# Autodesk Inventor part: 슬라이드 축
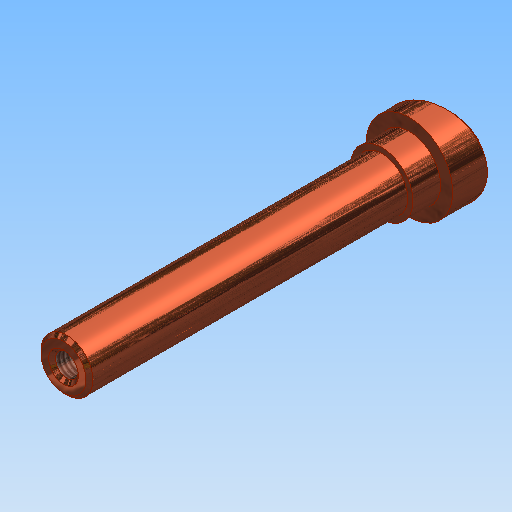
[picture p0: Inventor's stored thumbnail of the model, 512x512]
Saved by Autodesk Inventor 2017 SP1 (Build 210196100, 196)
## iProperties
Created: 2021-07
Part Number: 슬라이드 축
Document SubType Name: 모델링
Designer: mdu
Mass: 21.572 g
Surface Area: 67.5858 cm^2
Volume: 21.572 cm^3
Density: 1 g/cm^3
Material: 일반
Appearance: 금속 1400F 열
변환 표준: STEP AP214IS
파일 이름: C:\Users\SeoGD\Desktop\?쒗뿕\異?stp
전처리기: Build: 253, Release: 2010 SP1 - Date: Wed 07/29/2009
전송 단위: 밀리미터
불확실성: 0.01
Author: mdu
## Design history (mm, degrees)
sketch "스케치1"
  geometry: L1 (0, 100)-(7.5, 100); L2 (7.5, 100)-(7.5, 0); L3 (7.5, 0)-(12.5, 0); L4 (12.5, 0)-(12.5, -17); L5 (12.5, -17)-(0, -17); L6 (0, -17)-(0, 100); 1 further point
  constraints: 12 end point, 2 parallel, 2 point on line, 1 perpendicular, 1 vertical
  dimensions: "d0" = 100 distance from line of L1 point (0, 0); "d1" = 15 diameter of L2 L6; "d2" = 25 diameter of L4 L6; "d3" = 17 distance of L3.end L4.end
revolve "회전1" sketch "스케치1" stored, may be unused: angle "d4" = 90 deg
sketch "스케치2"
  geometry: L1 (12.5, 0)-(12.5, -17) reference; L2 (-12.5, -17)-(12.5, -17) reference; L3 (-12.5, 0)-(-12.5, -17) reference; L4 (12.5, -5)-(-12.5, -11.699); L5 (-12.5, 0)-(12.5, 0) reference; 1 further point
  constraints: 2 end point, 2 point on line
  dimensions: "d5" = 75 deg angle of L1 L4; "d6" = 5 distance from line of L4.start L5
extrude "돌출1" cut sketch "스케치2" stored distance "d7" = 10; taper "d8" = 0 deg
chamfer "모따기1" distance "d9" = 1; stored, may be unused: second distance "d10" = 2, angle "d11" = 45 deg
fillet "모깎기1" dims "d12" = 0.5
hole "구멍1" diameter "d15" = 6.647; stored, may be unused: countersink angle "d19" = 90 deg, drill point angle "d21" = 118 deg; dims "d13" = 10, "d14" = 10, "d16" = 17, "d17" = 4, "d18" = 2, "d20" = 20
chamfer "모따기2" distance "d22" = 1; stored, may be unused: second distance "d23" = 2, angle "d24" = 45 deg
sketch "스케치3"
  geometry: C1 r 9 at (0, 0); 1 further point
  constraints: 1 centre point, 1 coincident
  dimensions: "d25" = 18 diameter of C1
extrude "돌출2" join sketch "스케치3" distance "d26" = 8; taper "d27" = 0 deg
node "솔리드1"
node "솔리드 본체"
node "곡면 본체"
node "솔리드2"
